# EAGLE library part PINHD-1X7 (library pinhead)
PIN HEADER
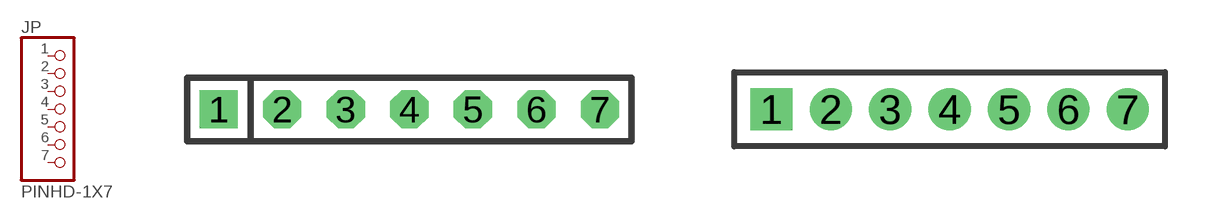
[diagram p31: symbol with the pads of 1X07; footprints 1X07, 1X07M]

Designator prefix JP

## PINHD-1X7  [1X07]
1  1  pas
2  2  pas
3  3  pas
4  4  pas
5  5  pas
6  6  pas
7  7  pas

## PINHD-1X7M  [1X07M]
Pads as for 1X07

## Footprint 1X07 (pad centres in mm)
PIN HEADER - 0.1"
drill 1.016 square: 1 -7.62,0
drill 1.016 octagon: 2 -5.08,0; 3 -2.54,0; 4 0,0; 5 2.54,0; 6 5.08,0; 7 7.62,0

## Footprint 1X07M (pad centres in mm)
PIN HEADER - 2MM"
drill 0.914 square: 1 -6,0
drill 0.914 round: 2 -4,0; 3 -2,0; 4 0,0; 5 2,0; 6 4,0; 7 6,0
